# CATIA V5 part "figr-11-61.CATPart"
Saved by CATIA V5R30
Part number: Part1
Bounding box of the stored display mesh (mm): x -54 to 54, y -91.936 to 93.838, z -12.649 to 110.643
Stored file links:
  D:\PROJECTS\CATIA V56R 2020\Resources\Parts File\c11_catia_v5_6r2020_prt\figr-11-61.CATPart
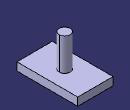
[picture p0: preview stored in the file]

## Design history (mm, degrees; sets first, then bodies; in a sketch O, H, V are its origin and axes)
Set1
  Loft1: Sections (Sketch4; Sketch3)
Body1 (main body)
  Sketch1 on yz-plane, origin (0, 0, 0), H (0, 1, 0), V (0, 0, 1)
    point P1 (93.8379, 11.643)
    line L1 (93.8379, 11.643) -> (93.8379, -12.6487)
    line L2 (93.8379, -12.6487) -> (-91.9362, -12.6487)
    line L3 (-91.9362, -12.6487) -> (-91.9362, 11.643)
    line L4 (-91.9362, 11.643) -> (93.8379, 11.643)
    point P5 (93.8379, 11.643)
    vertical: L1 V, L3 V
    horizontal: L2 H, L4 H
    coincidence: P5 P1
  Pad1: profile Sketch1, direction (1, 0, 0), length 54, mirrored extent
  Sketch2 on face of Pad1, origin (0, 0, 11.643), H (1, 0, 0), V (0, 1, 0)
    circle A1 centre (0, 0) radius 16.7533
    point P1 (16.7533, 0)
    coincidence: A1 P1, P1 H
  Pad2: profile Sketch2, direction (0, 0, 1), length 99
  Sketch3 on face of Pad2, origin (0, 0, 110.643), H (1, 0, 0), V (0, 1, 0)
    point P1 (0, 42.8937)
    point P2 (33.9651, 0)
    projected circle E1 centre (0, 0) radius 16.7533 from edge [face of Pad2 | face of Pad2]
    circle A1 centre (0, 0) radius 33.9651
    point P3 (0, 33.9651)
    coincidence: P1 V, P2 H, A1 P2, A1 P3, P3 V
  Sketch4 on face of Pad1, origin (0, 0, 11.643), H (1, 0, 0), V (0, 1, 0)
    ellipse A1 centre (0, 0) semi-axes 69.9141, 43.1918 rotation 90
    point P1 (0, 69.9141)
    point P2 (43.1918, 0)
    coincidence: P1 V, P2 H, A1 P1, A1 P2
